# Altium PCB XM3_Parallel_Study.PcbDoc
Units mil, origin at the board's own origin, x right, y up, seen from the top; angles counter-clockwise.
Board outline 10000 x 11930 mil, 4 copper layers (TOP, LAYER2, LAYER3, BOTTOM), stack 92 mil thick; 58 components, 13 nets, 178 pads, 387 vias.
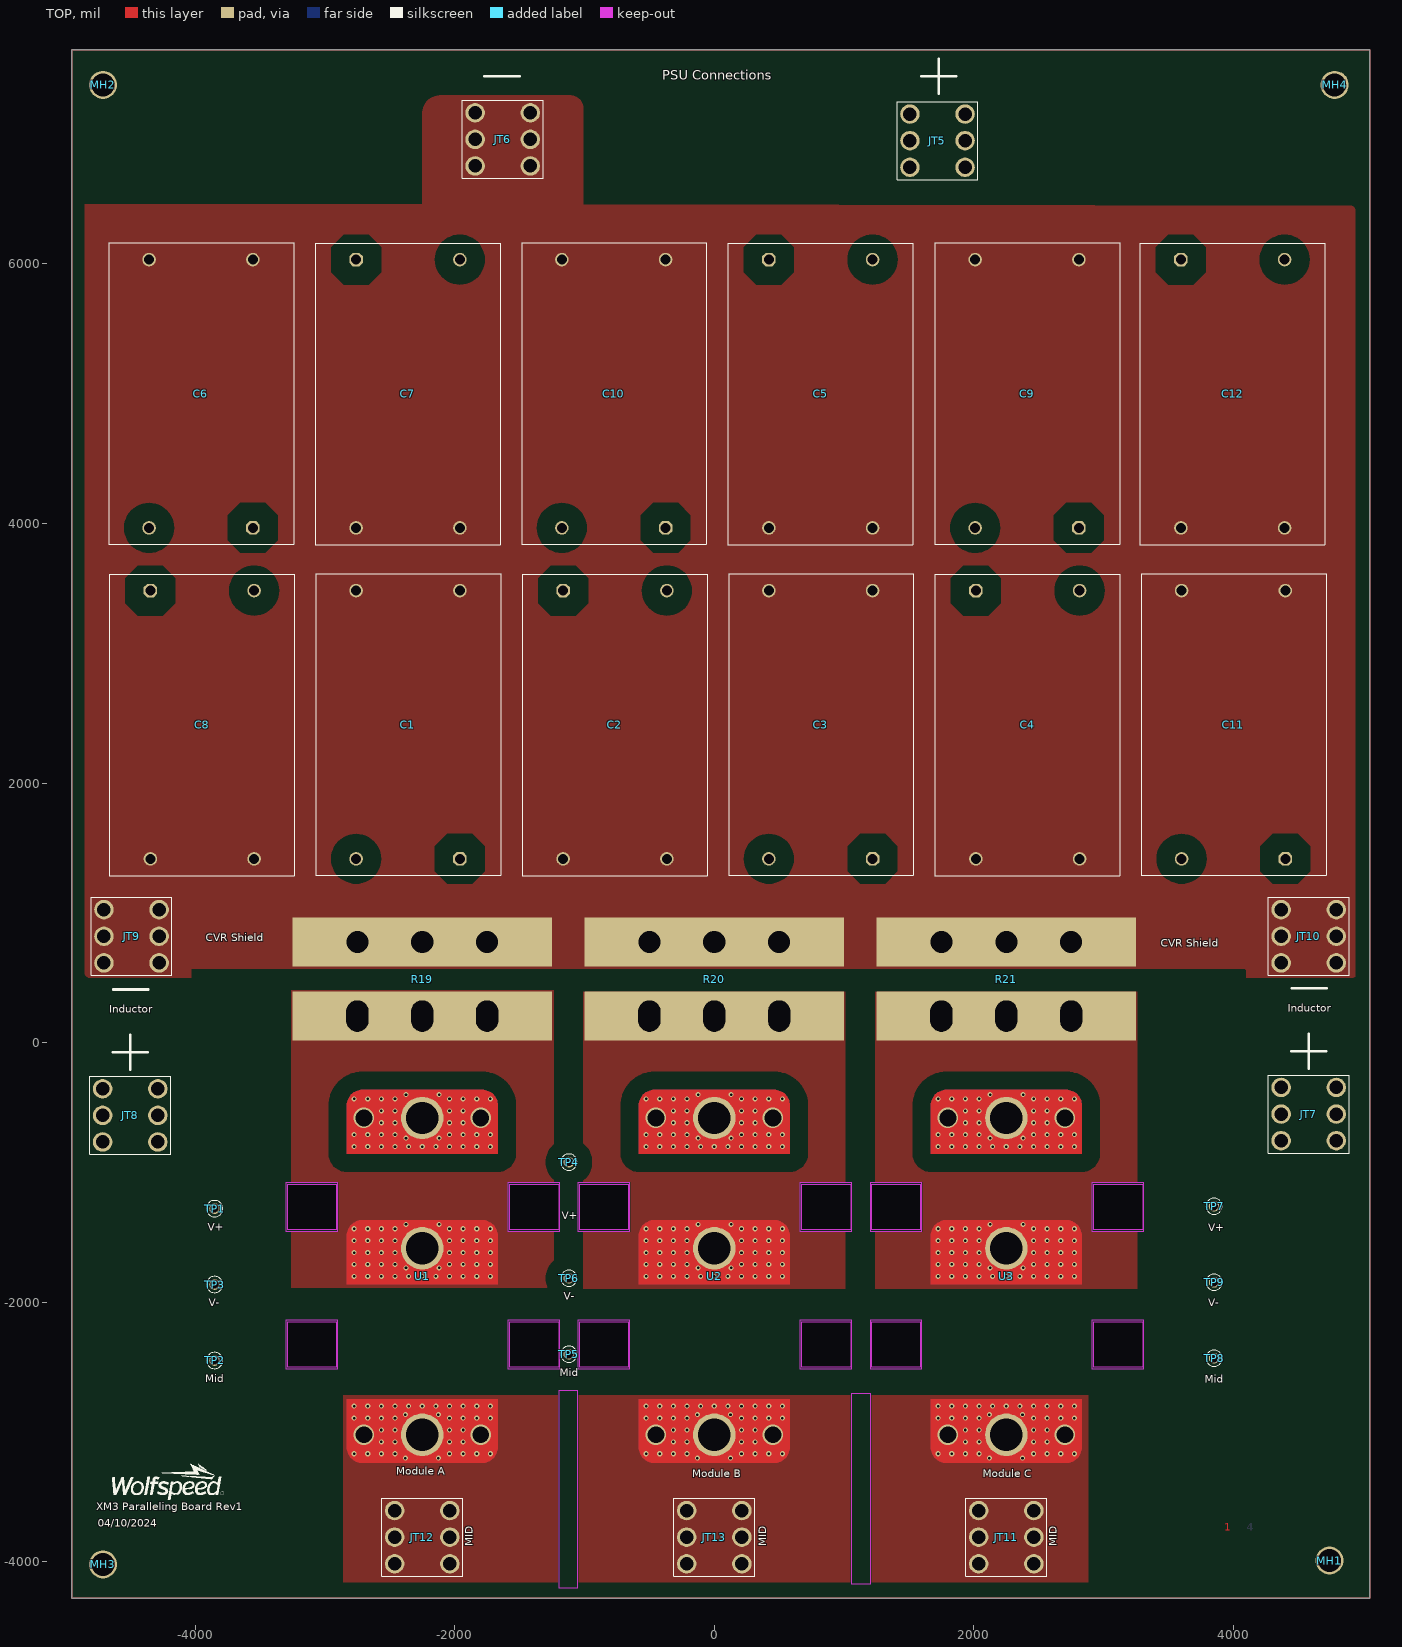
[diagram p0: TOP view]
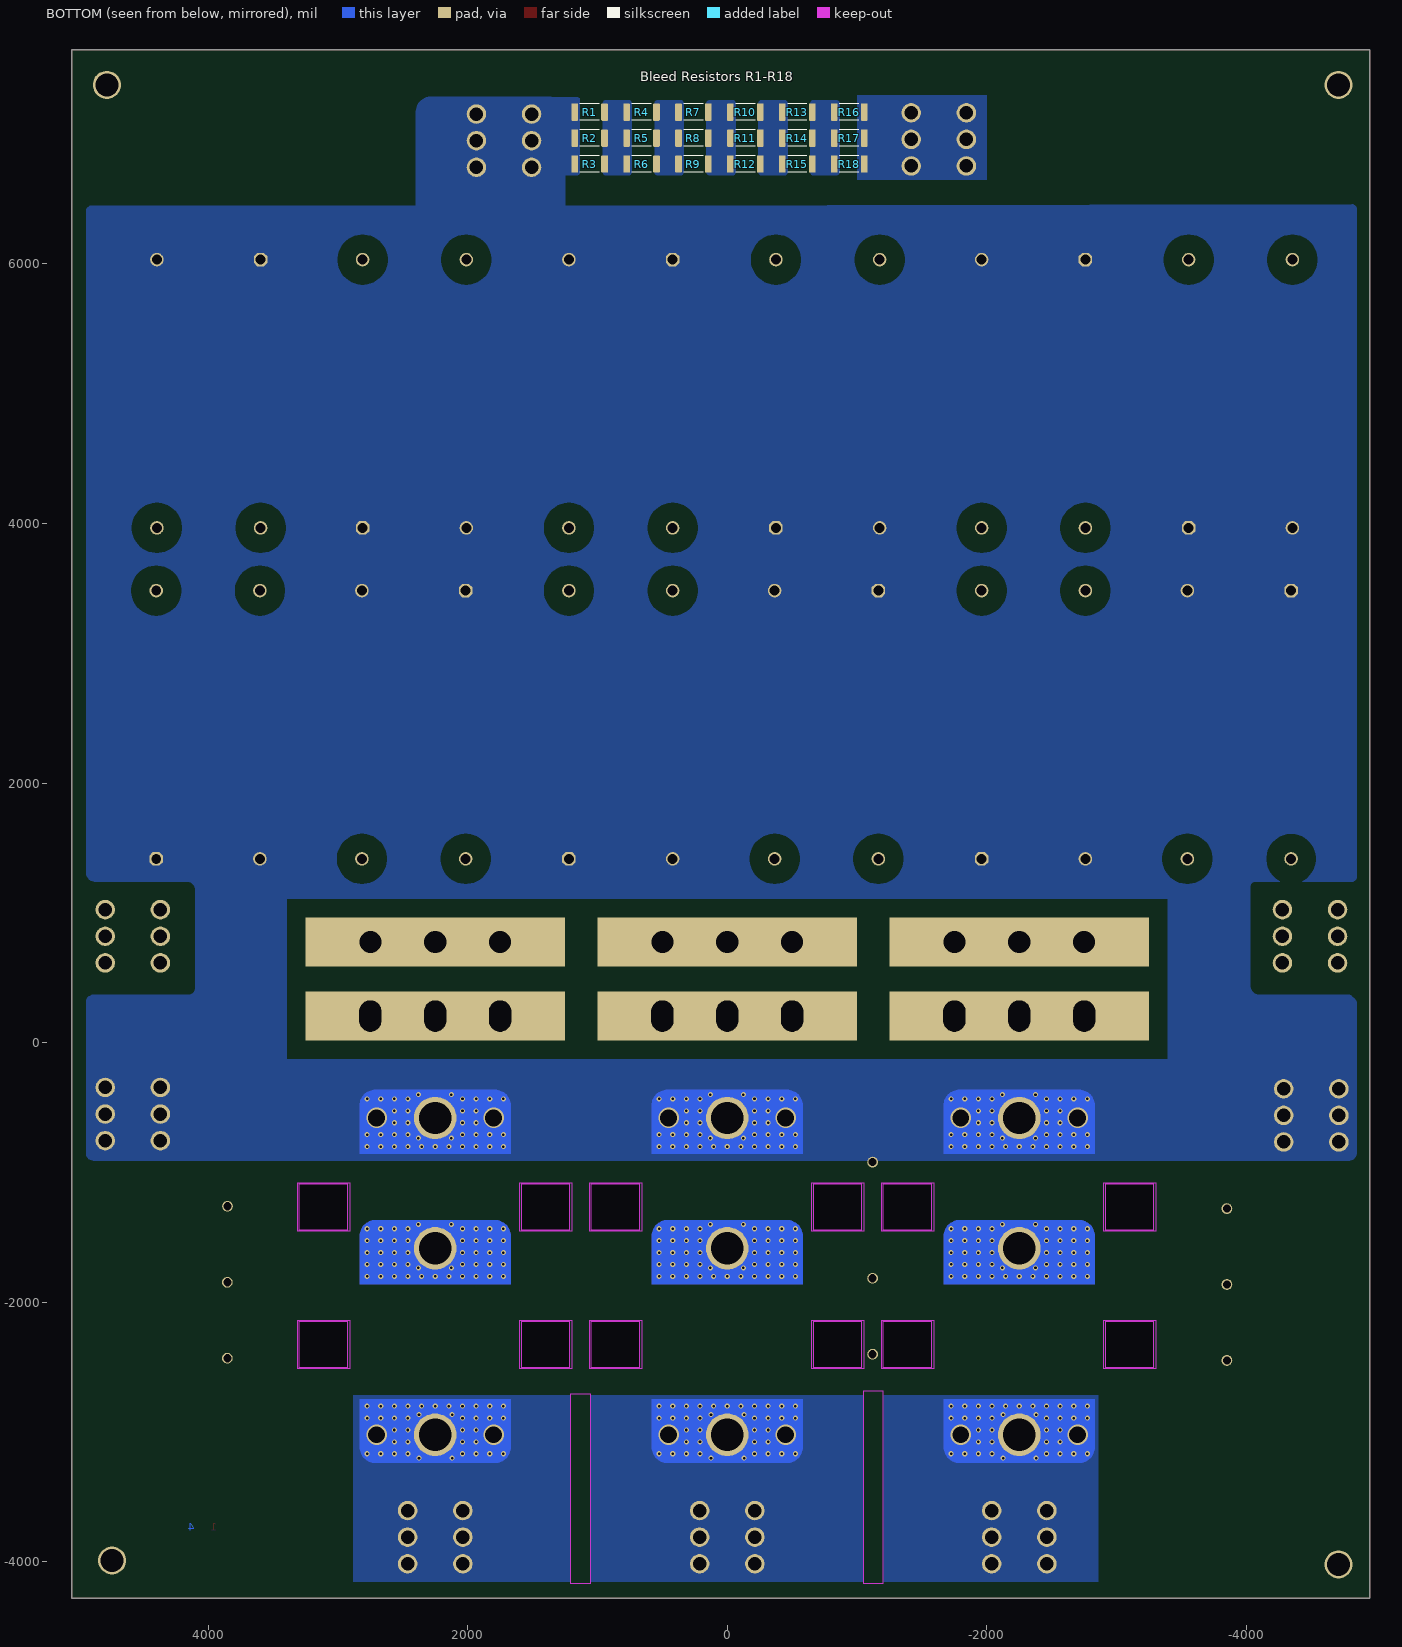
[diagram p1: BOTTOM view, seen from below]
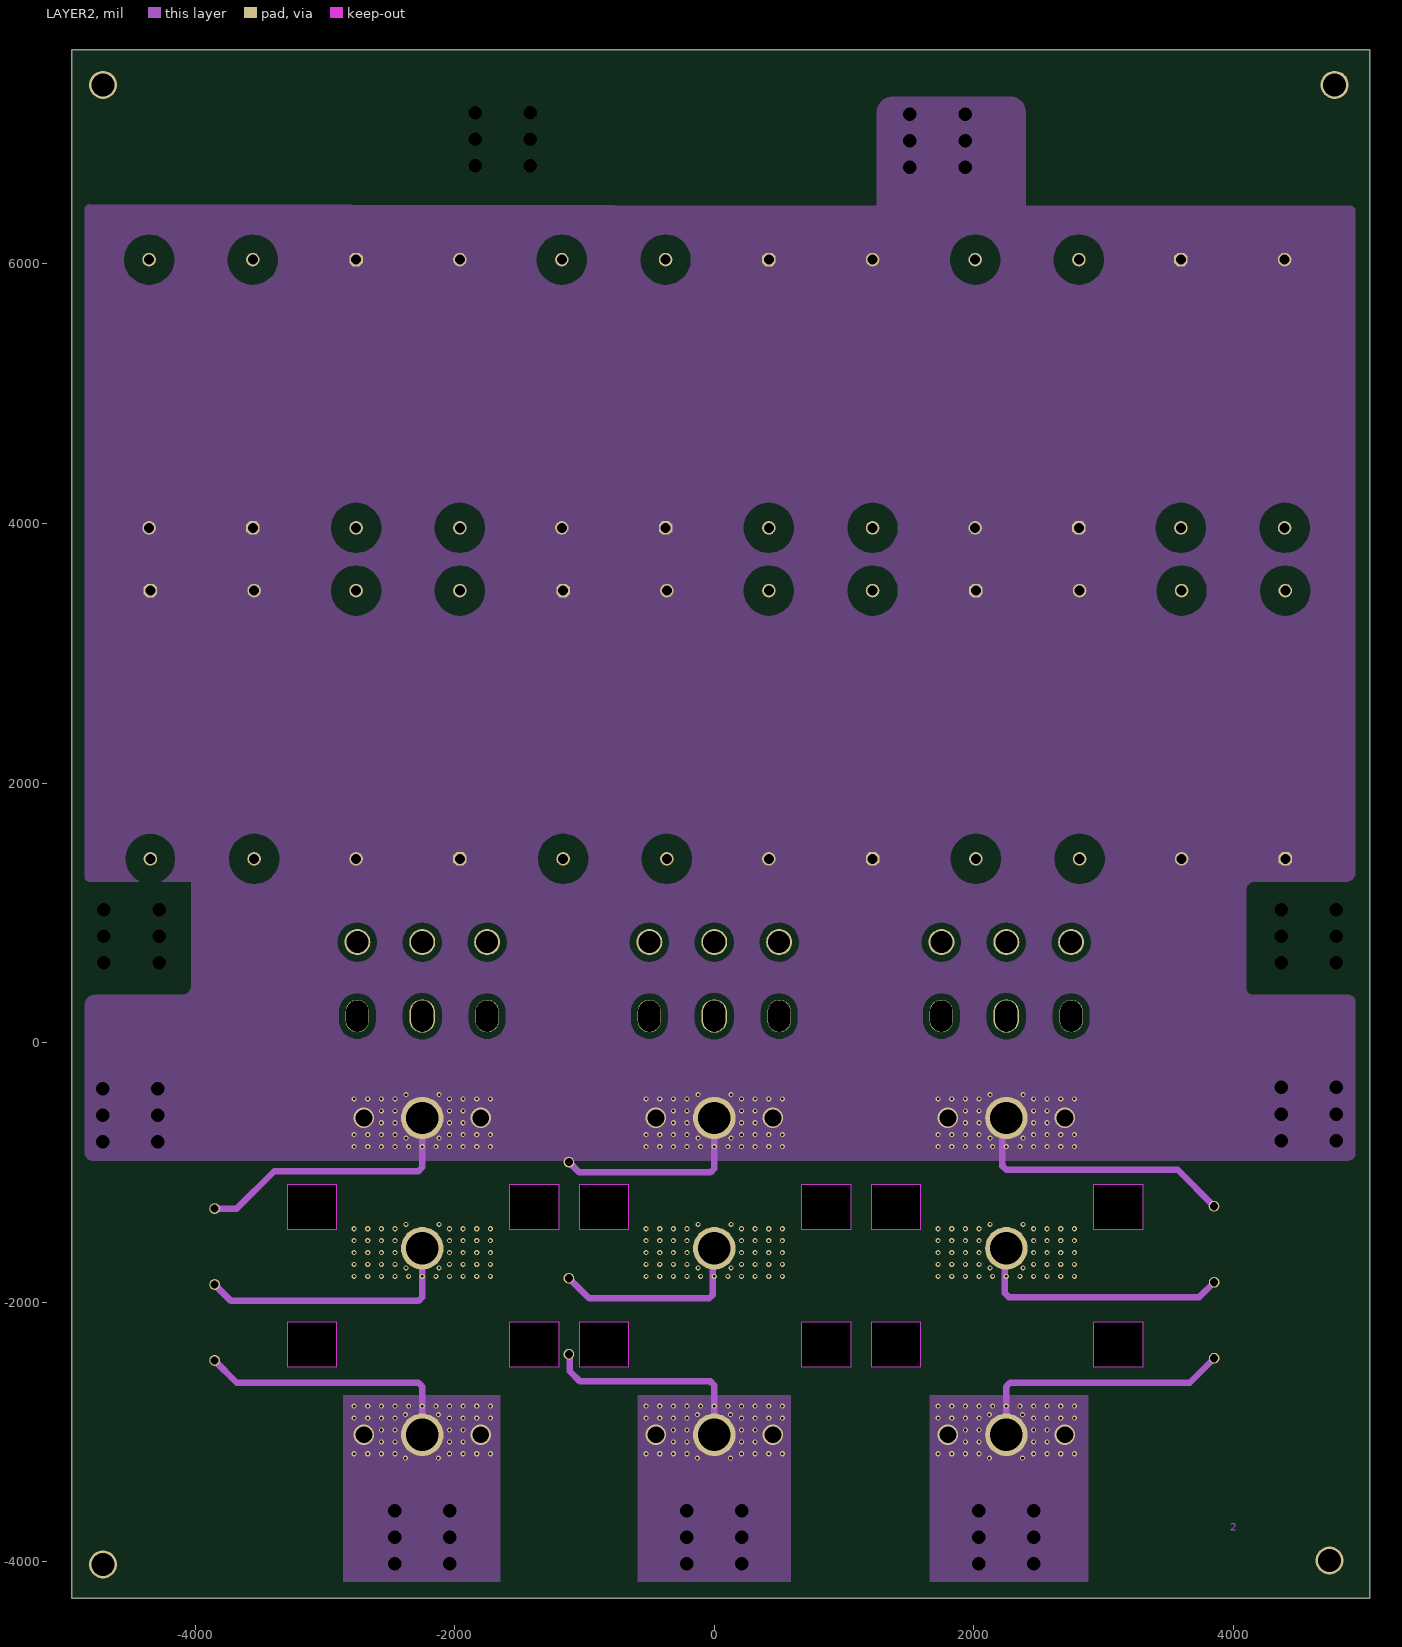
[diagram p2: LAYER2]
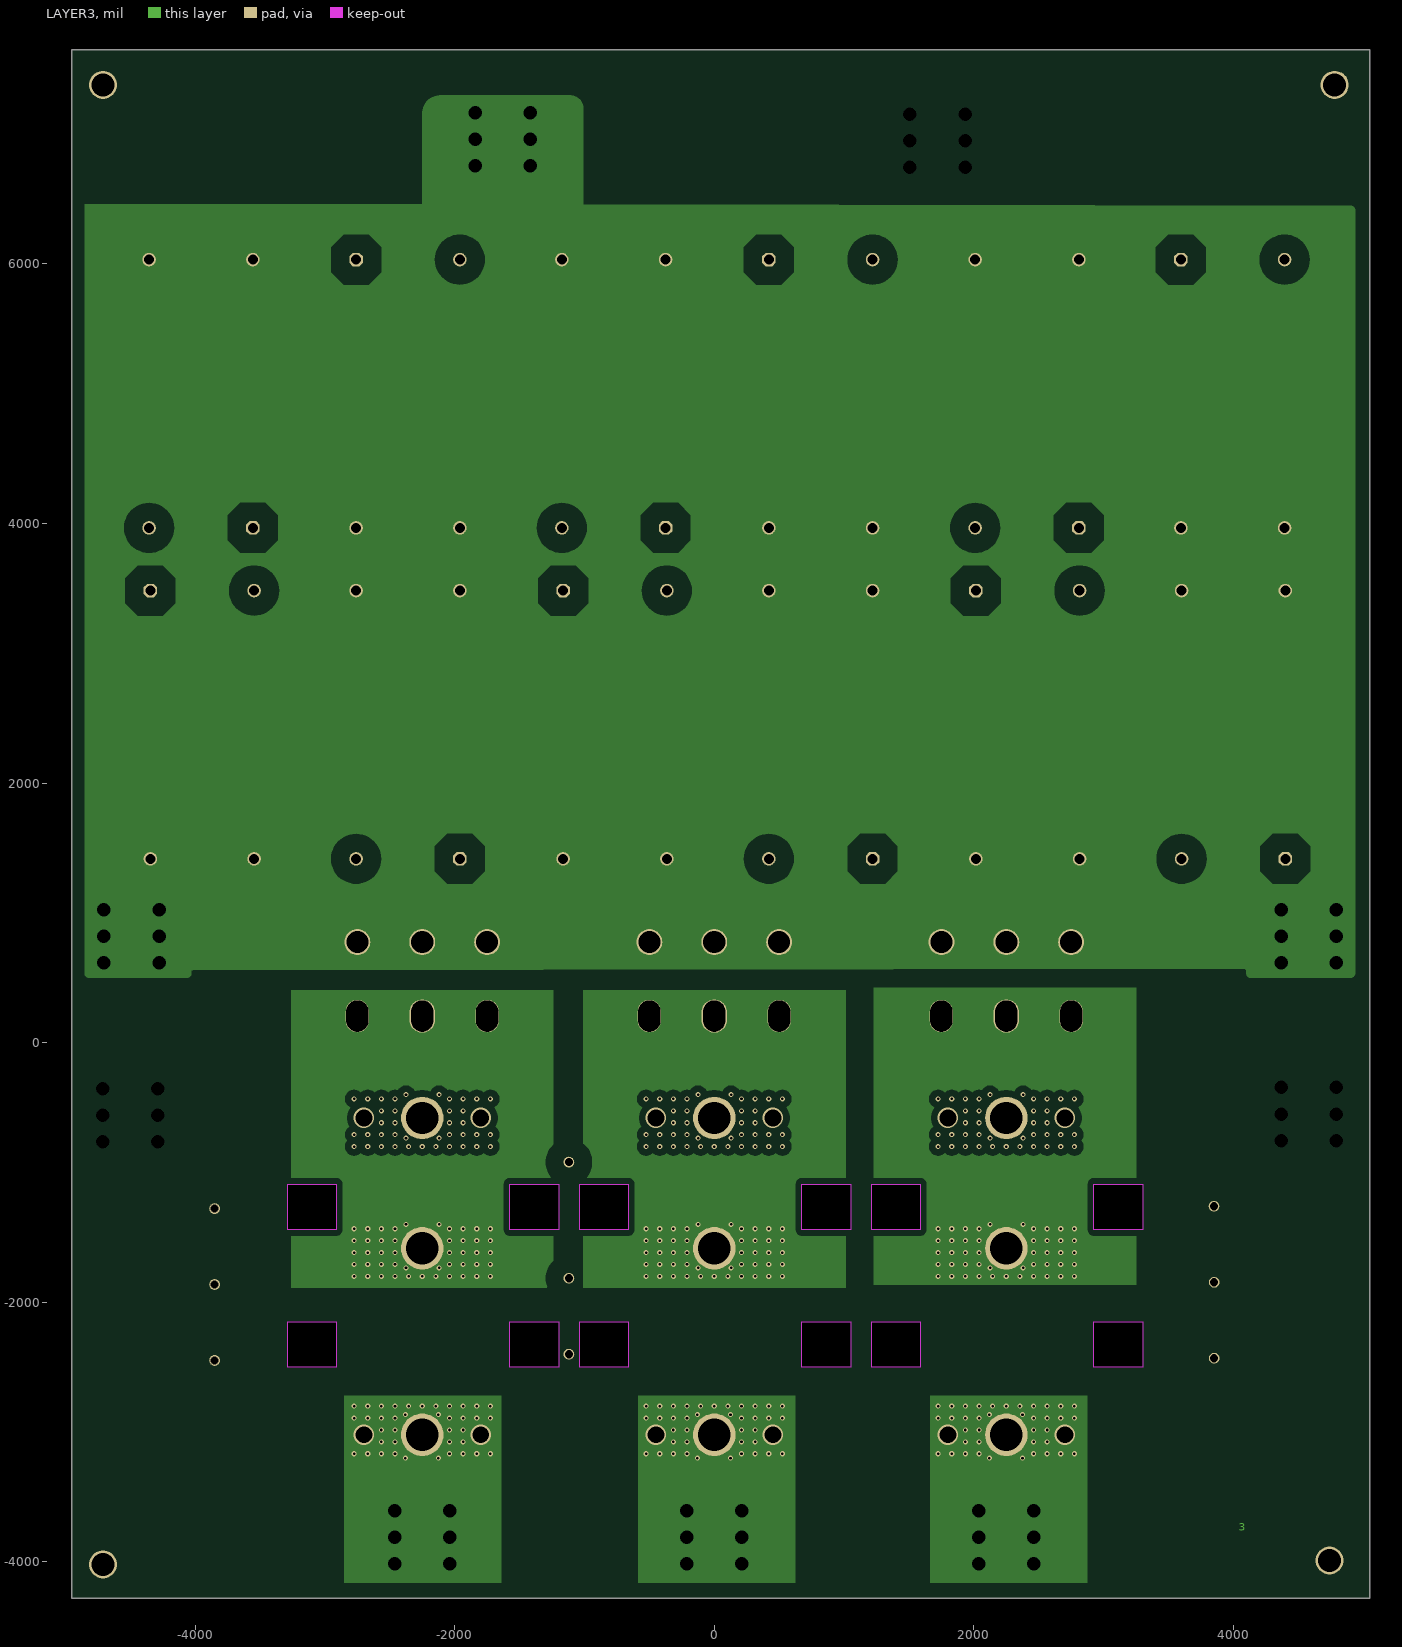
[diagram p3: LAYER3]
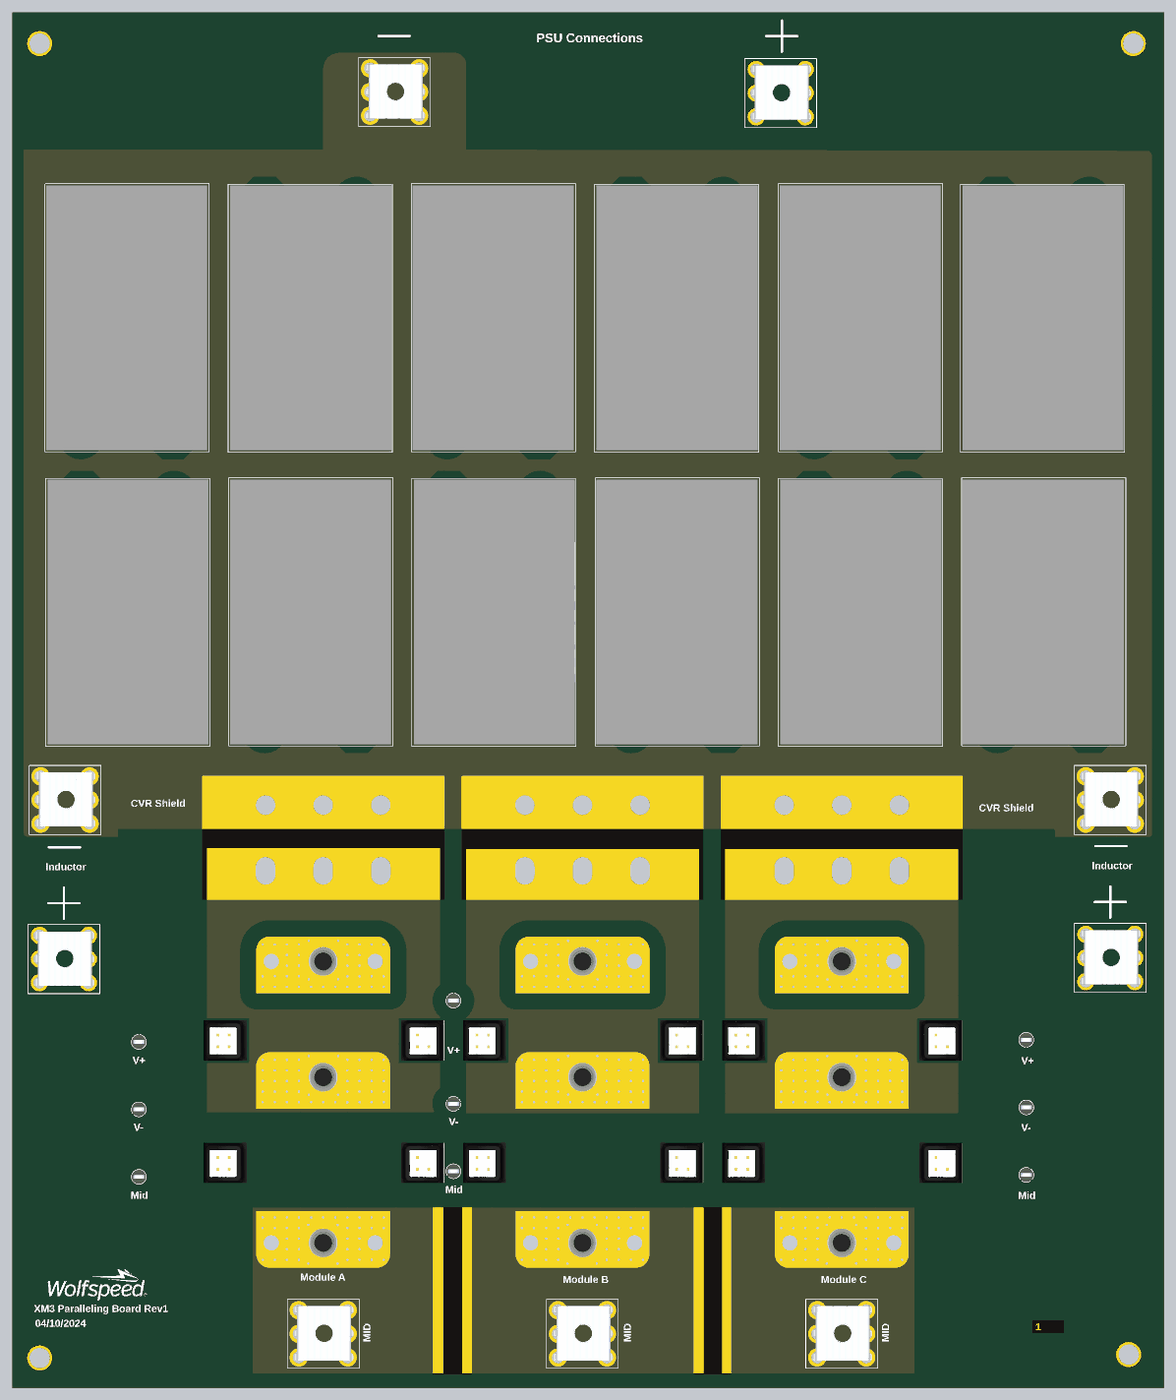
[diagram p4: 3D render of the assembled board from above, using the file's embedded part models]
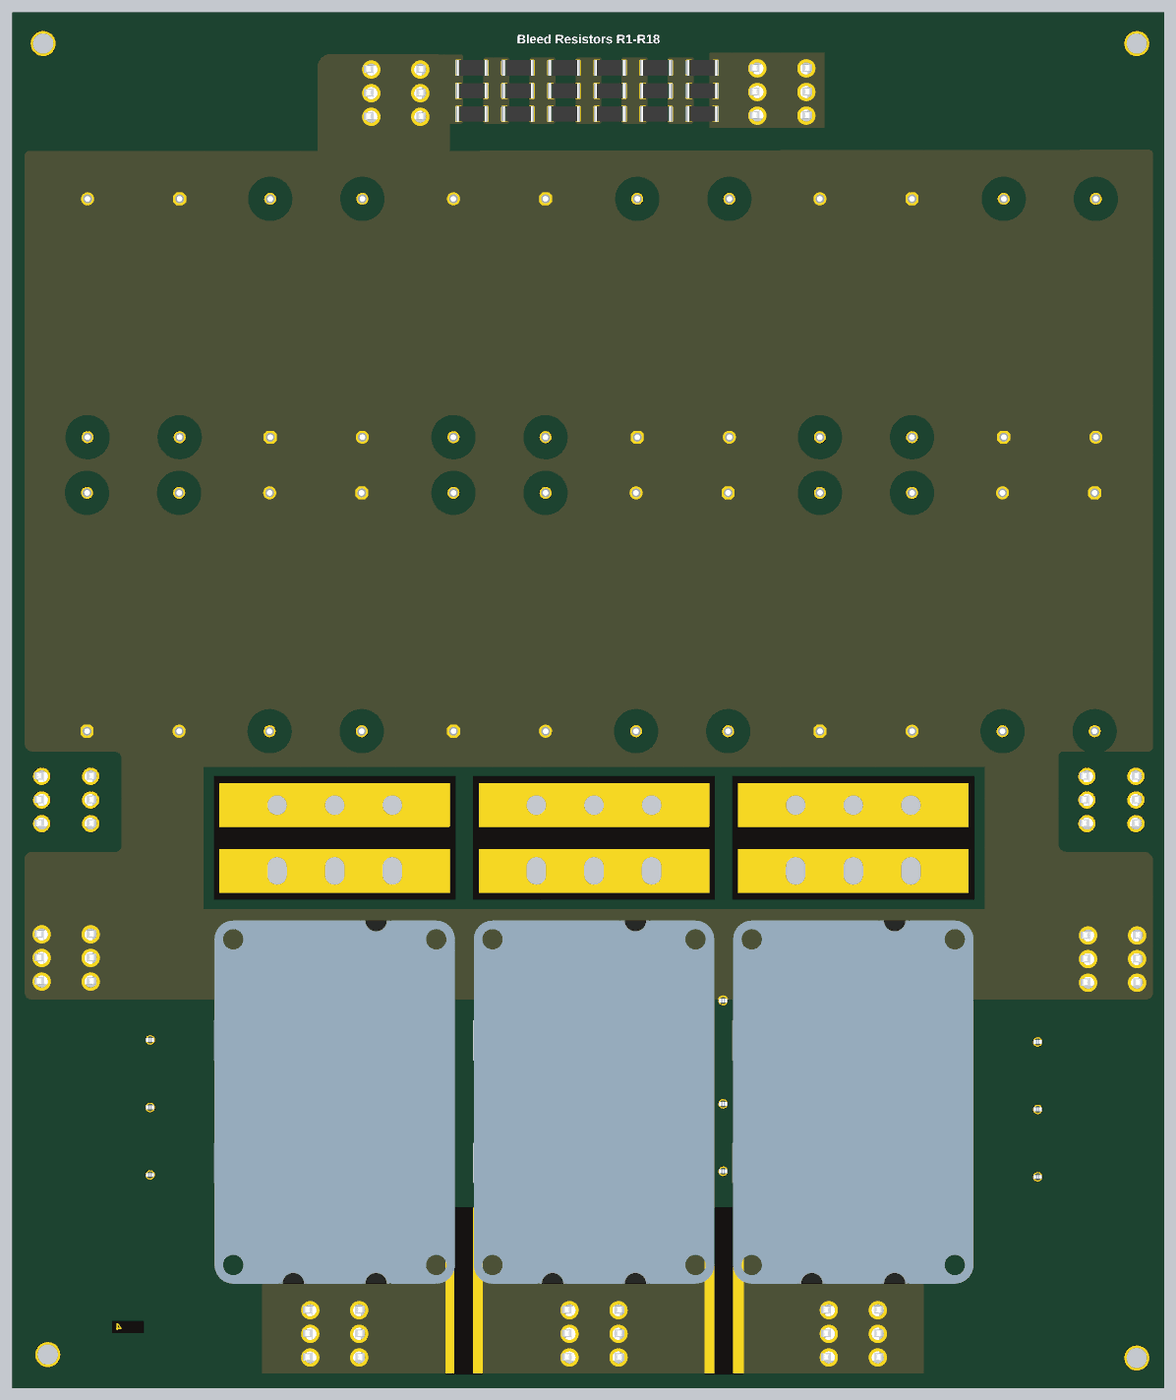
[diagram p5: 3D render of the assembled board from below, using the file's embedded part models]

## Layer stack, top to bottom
TOP: signal copper 2.68
Dielectric 1: core 8, FR-4, Dk 4.5
LAYER2: signal copper 2.68
Dielectric2: core 65.28, FR-4, Dk 4.5
LAYER3: signal copper 2.68
Dielectric3: core 8, FR-4, Dk 4.5
BOTTOM: signal copper 2.68

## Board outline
-4950,-4280 -4950,7650 5050,7650 5050,-4280

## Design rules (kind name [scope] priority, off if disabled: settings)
Clearance HiPot_Clearance_Inner2 [OnLayer('LAYER2') vs InComponent('R19') OR InComponent('R20') OR InComponent('R21') OR InComponent('U1')  OR InComponent('U2')  OR InComponent('U3')] p1: gap=50 ignorepadtopadclearanceinfootprint=TRUE
Clearance HiPot_Clearance_Inner3 [OnLayer('LAYER3') vs InComponent('R19') OR InComponent('R20') OR InComponent('R21') OR InComponent('U1')  OR InComponent('U2')  OR InComponent('U3')] p2: gap=50 ignorepadtopadclearanceinfootprint=TRUE
Clearance HiPot_Clearance [InNetClass('HighPotential') vs InNetClass('HighPotential')] p3: gap=140 ignorepadtopadclearanceinfootprint=TRUE
Clearance [All] p4: gap=6 ignorepadtopadclearanceinfootprint=FALSE
Height [All] p1: minheight=0 maxheight=3000 prefheight=500
HoleSize [All] p1: absolutevalues=TRUE maxlimit=1000 minlimit=1 maxpercent=80.000 minpercent=20.000
PlaneClearance [All] p1: clearance=275.59
PlaneConnect [All] p1: planeconnectstyle=Direct reliefexpansion=20 reliefentries=4 reliefconductorwidth=10 reliefairgap=10
PolygonConnect [All] p1: connectstyle=Direct reliefconductorwidth=10 reliefentries=4 polygonreliefangle="90 Angle" airgapwidth=10
RoutingVias [All] p1: holewidth=28 width=50 viastyle="Through Hole" minholewidth=5 minwidth=8 maxholewidth=28 maxwidth=50
SolderMaskExpansion [All] p1: expansion=4 istentingtop=FALSE
Width [All] p1: maxlimit=500 minlimit=5 preferedwidth=50 minimp=50.000000 maximp=50.000000 favimp=50.000000
26 further rules are at their usual default settings.

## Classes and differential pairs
net class HighPotential: +VIN -Vin Midpoint S1 S2 S3

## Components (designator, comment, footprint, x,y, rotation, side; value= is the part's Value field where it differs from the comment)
C1 "B32778G0406K000" C4AQSBW5220A3NJ -2360,2450 r180 top value=40uF
C2 "B32778G0406K000" C4AQSBW5220A3NJ -765,2450 r0 top value=40uF
C3 "B32778G0406K000" C4AQSBW5220A3NJ 820,2450 r180 top value=40uF
C4 "B32778G0406K000" C4AQSBW5220A3NJ 2415,2450 r0 top value=40uF
C5 "B32778G0406K000" C4AQSBW5220A3NJ 820,5000 r0 top value=40uF
C6 "B32778G0406K000" C4AQSBW5220A3NJ -3955,5000 r180 top value=40uF
C7 "B32778G0406K000" C4AQSBW5220A3NJ -2360,5000 r0 top value=40uF
C8 "B32778G0406K000" C4AQSBW5220A3NJ -3945,2450 r0 top value=40uF
C9 "B32778G0406K000" C4AQSBW5220A3NJ 2410,5000 r180 top value=40uF
C10 "B32778G0406K000" C4AQSBW5220A3NJ -775,5000 r180 top value=40uF
C11 "B32778G0406K000" C4AQSBW5220A3NJ 4000,2450 r180 top value=40uF
C12 "B32778G0406K000" C4AQSBW5220A3NJ 3995,5000 r0 top value=40uF
JT5 "8196" 8196 1720,6950 r90 top
JT6 "8196" 8196 -1630,6960 r90 top
JT7 "8196" 8196 4580,-550 r90 top
JT8 "8196" 8196 -4500,-560 r90 top
JT9 "8196" 8196 -4490,820 r90 top
JT10 "8196" 8196 4580,820 r90 top
JT11 "8196" 8196 2250,-3810 r90 top
JT12 "8196" 8196 -2250,-3810 r90 top
JT13 "8196" 8196 0,-3810 r90 top
MH1 "MountingHole" MountingHole4mm5#1 4740,-3990 r0 top
MH2 "MountingHole" MountingHole4mm5#2 -4710,7400 r0 top
MH3 "MountingHole" MountingHole4mm5#1 -4710,-4020 r0 top
MH4 "MountingHole" MountingHole4mm5#1 4780,7380 r0 top
R1 "2176071-6" RESC6432X06N 1060.43,7170 r180 bottom
R2 "2176071-6" RESC6432X06N 1060.43,6970 r180 bottom
R3 "2176071-6" RESC6432X06N 1060.43,6770 r180 bottom
R4 "2176071-6" RESC6432X06N 660.43,7170 r180 bottom
R5 "2176071-6" RESC6432X06N 660.43,6970 r180 bottom
R6 "2176071-6" RESC6432X06N 660.43,6770 r180 bottom
R7 "2176071-6" RESC6432X06N 260.43,7170 r180 bottom
R8 "2176071-6" RESC6432X06N 260.43,6970 r180 bottom
R9 "2176071-6" RESC6432X06N 260.43,6770 r180 bottom
R10 "2176071-6" RESC6432X06N -139.57,7170 r180 bottom
R11 "2176071-6" RESC6432X06N -139.57,6970 r180 bottom
R12 "2176071-6" RESC6432X06N -139.57,6770 r180 bottom
R13 "2176071-6" RESC6432X06N -539.57,7170 r180 bottom
R14 "2176071-6" RESC6432X06N -539.57,6970 r180 bottom
R15 "2176071-6" RESC6432X06N -539.57,6770 r180 bottom
R16 "2176071-6" RESC6432X06N -939.57,7170 r180 bottom
R17 "2176071-6" RESC6432X06N -939.57,6970 r180 bottom
R18 "2176071-6" RESC6432X06N -939.57,6770 r180 bottom
R19 "W-2-005-2FC" W-2-005-2FC_3HOLE -2250,480 r180 top
R20 "W-2-005-2FC" W-2-005-2FC_3HOLE 0,480 r180 top
R21 "W-2-005-2FC" W-2-005-2FC_3HOLE 2250,480 r180 top
TP1 "5011" KSTN-5011_V -3850,-1278.23 r0 top
TP2 "5011" KSTN-5011_V -3850,-2448.23 r0 top
TP3 "5011" KSTN-5011_V -3850,-1863.23 r0 top
TP4 "5011" KSTN-5011_V -1120,-920 r0 top
TP5 "5011" KSTN-5011_V -1120,-2400 r0 top
TP6 "5011" KSTN-5011_V -1120,-1815 r0 top
TP7 "5011" KSTN-5011_V 3850.76,-1260.29 r0 top
TP8 "5011" KSTN-5011_V 3851.53,-2431.06 r0 top
TP9 "5011" KSTN-5011_V 3851.53,-1846.06 r0 top
U1 "XM_Module" "XM MODULE" -2250,-1800.47 r0 top
U2 "XM_Module" "XM MODULE" 0,-1800.47 r0 top
U3 "XM_Module" "XM MODULE" 2250,-1800.47 r0 top

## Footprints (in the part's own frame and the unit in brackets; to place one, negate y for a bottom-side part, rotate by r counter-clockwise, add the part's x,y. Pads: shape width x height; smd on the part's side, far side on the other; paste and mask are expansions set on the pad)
8196 [mil]
  round 150 / inner round 60 / far side round 150 hole 103.94: 1(-205,-212.5) 2(0,-212.5) 3(205,-212.5) 4(205,212.5) 5(0,212.5) 6(-205,212.5)
  silkscreen extent -300,-312 300,312, body extent -230,-278 240,262, height 454
C4AQSBW5220A3NJ [mm] "C4AQSBW5220A3NJ Unchecked Film; Metallized Polypropylene; DC Link; C4AQ; Automotive Grade; 22 uF; 5%; 1; 50 Film Capacitors 8.13"
  oct 2.65x2.65 hole 1.95: 1(-10.15,26.25)
  round 2.65 hole 1.95: 2(10.15,26.25) 3(-10.15,-26.25) 4(10.15,-26.25)
  silkscreen extent -18.16,-29.59 18.03,29.46, body extent -17.73,-29.15 17.78,29.15, height 50.31
KSTN-5011_V [mm] "Test Point, Dia 3.17mm"
  round 2.1 hole 1.6: 1(0,0)
  silkscreen extent -1.59,-1.58 1.59,1.58, body extent -1.59,-1.59 1.59,1.59, height 8.13
MountingHole4mm5#1 [mm]
  round 5.5 hole 4.5: 3(0,0)
MountingHole4mm5#2 [mm]
  round 5.5 hole 4.5: 3(0,-0.508)
RESC6432X06N [mm] "Chip Resistor, 2-Leads, Body 6.35x3.20mm, IPC Medium Density"
  rrect25% 1.3x3.4 smd: 1(-2.925,0) 2(2.925,0)
  silkscreen extent -1.9,-1.6 1.9,1.6, body extent -3.22,-1.7 3.22,1.7, height 0.65
W-2-005-2FC_3HOLE [mil]
  oval 180x250 hole 170 slot 240 at 90 deg: 1(-500,275) 3(500,275)
  rect 2000x380 / inner oval 196.85x255.91 / far side rect 2000x380 hole 170 slot 240 at 90 deg: 2(0,275)
  round 200 hole 170: 4(-500,-295.28) 6(500,-295.28)
  rect 2000x380 / inner round 200 / far side rect 2000x380 hole 170: 5(0,-295.28)
"XM MODULE" [mm]
  round 8.3 hole 6.3: 1(0,-31) 2(0,5.5) 3(0,31)
  TOP region: -14.75,-24 14.75,-24 14.75,-33.452 14.518,-34.618 13.857,-35.607 12.868,-36.268 11.702,-36.5 11.702,-36.5 -11.702,-36.5 -12.868,-36.268 -13.857,-35.607 -14.518,-34.618 -14.75,-33.452 -14.75,-33.452 -14.75,-25
  TOP region: -14.75,-24 14.75,-24 14.75,-33.452 14.518,-34.618 13.857,-35.607 12.868,-36.268 11.702,-36.5 11.702,-36.5 -11.702,-36.5 -12.868,-36.268 -13.857,-35.607 -14.518,-34.618 -14.75,-33.452 -14.75,-33.452 -14.75,-25
  TOP region: -14.75,24 14.768,24 14.768,33.452 14.536,34.618 13.875,35.607 12.886,36.268 11.72,36.5 11.72,36.5 -11.702,36.5 -12.868,36.268 -13.857,35.607 -14.518,34.618 -14.75,33.452 -14.75,33.452 -14.75,28.75
  TOP region: -14.75,-1.5 14.75,-1.5 14.75,7.952 14.518,9.118 13.857,10.107 12.868,10.768 11.702,11 11.702,11 -11.702,11 -12.868,10.768 -13.857,10.107 -14.518,9.118 -14.75,7.952 -14.75,7.952 -14.75,2.236
  TOP keep-out region: -26.67,8.801 -16.51,8.801 -16.51,18.326 -26.67,18.326
  TOP keep-out region: 16.764,8.801 26.924,8.801 26.924,18.326 16.764,18.326
  TOP keep-out region: 16.764,-18.098 26.924,-18.098 26.924,-8.572 16.764,-8.572
  TOP keep-out region: -26.67,-18.098 -16.51,-18.098 -16.51,-8.572 -26.67,-8.572
  BOTTOM region: -14.75,24 14.768,24 14.768,33.452 14.536,34.618 13.875,35.607 12.886,36.268 11.72,36.5 11.72,36.5 -11.702,36.5 -12.868,36.268 -13.857,35.607 -14.518,34.618 -14.75,33.452 -14.75,33.452 -14.75,28.75
  BOTTOM region: -14.75,-1.5 14.75,-1.5 14.75,7.952 14.518,9.118 13.857,10.107 12.868,10.768 11.702,11 11.702,11 -11.702,11 -12.868,10.768 -13.857,10.107 -14.518,9.118 -14.75,7.952 -14.75,7.952 -14.75,2.236
  BOTTOM region: -14.75,-24 14.75,-24 14.75,-33.452 14.518,-34.618 13.857,-35.607 12.868,-36.268 11.702,-36.5 11.702,-36.5 -11.702,-36.5 -12.868,-36.268 -13.857,-35.607 -14.518,-34.618 -14.75,-33.452 -14.75,-33.452 -14.75,-25
  BOTTOM keep-out region: 16.764,8.801 26.924,8.801 26.924,18.326 16.764,18.326
  BOTTOM keep-out region: 16.764,-18.098 26.924,-18.098 26.924,-8.572 16.764,-8.572
  BOTTOM keep-out region: -26.67,-18.098 -16.51,-18.098 -16.51,-8.572 -26.67,-8.572
  BOTTOM keep-out region: -26.67,8.801 -16.51,8.801 -16.51,18.326 -26.67,18.326
  Keep-Out Layer board cut-out: 17.145,18.034 26.67,18.034 26.67,9.144 17.145,9.144
  Keep-Out Layer board cut-out: 17.145,-8.89 26.67,-8.89 26.67,-17.78 17.145,-17.78
  Keep-Out Layer board cut-out: -26.352,-8.89 -16.828,-8.89 -16.828,-17.78 -26.352,-17.78
  Keep-Out Layer board cut-out: -26.352,18.034 -16.828,18.034 -16.828,9.144 -26.352,9.144
  body extent -26.5,-40 26.5,40, height 15.76

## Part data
C1 C2 C3 C4 C5 C6 C7 C8 C9 C10 C11 C12: "B32778G0406K000 Unchecked Film; Metallized Polypropylene; DC Link; C4AQ; Automotive Grade; 40 uF; 5%; 1; 50 Film Capacitors 8.13", Manufacturer=Kemet, Tolerence=5%, Voltage Rating=1500VDC
JT5 JT6 JT7 JT8 JT9 JT10 JT11 JT12 JT13: library part "Conn Plug 6", "TERMINAL SCREW PC HEAVY DUTY", Manufacturer="Keystone Electronics"
R1 R2 R3 R4 R5 R6 R7 R8 R9 R10 R11 R12 R13 R14 R15 R16 R17 R18: "Res Thick Film 2512 220K Ohm 1% 2W ±100ppm/°C Molded SMD T/R", Case Code (Imperial)=2512, Case Code (Metric)=6432, Manufacturer="TE Connectivity", Max Operating Temperature=155°C, Max Power Dissipation=2W, Min Operating Temperature=-55°C, Package Quantity=4000, Resistance=220kR, Resistor Type="Thick Film", Supplier Part Number 1=01AH0733, Temperature Coefficient=100ppm/°C, Tolerance=1%
TP1 TP2 TP3 TP4 TP5 TP6 TP7 TP8 TP9: "Test Point, Black, Through Hole, RoHS, Bulk", Colour=Black, Manufacturer=Keystone, Package Quantity=100

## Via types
v1: diameter 39.37, hole 19.68, TOP to BOTTOM, 375 vias
v2: diameter 157.48, hole 129.92, TOP to BOTTOM, 12 vias

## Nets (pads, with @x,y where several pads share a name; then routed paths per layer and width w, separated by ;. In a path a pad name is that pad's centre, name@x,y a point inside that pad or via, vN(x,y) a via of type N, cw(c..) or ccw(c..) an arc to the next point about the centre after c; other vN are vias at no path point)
+VIN: C1.1 C1.2 C2.1 C2.2 C3.1 C3.2 C4.1 C4.2 C5.1 C5.2 C6.1 C6.2 C7.1 C7.2 C8.1 C8.2 C9.1 C9.2 C10.1 C10.2 C11.1 C11.2 C12.1 C12.2 JT5.1 JT5.2 JT5.3 JT5.4 JT5.5 JT5.6 JT7.1 JT7.2 JT7.3 JT7.4 JT7.5 JT7.6 JT8.1 JT8.2 JT8.3 JT8.4 JT8.5 JT8.6 R1.1 R2.1 R3.1 TP1.1 TP4.1 TP7.1 U1.3 U2.3 U3.3 | length 5810.4
  LAYER2 w50: TP1.1 -3678.23,-1278.23 -3390,-990 -2279.29,-990 -2250,-960.71 v1(-2250,-800.47) U1.3 ; TP4.1 -1040,-1000 -29.29,-1000 0,-970.71 v1(0,-800.47) U2.3 ; U3.3 2220,-610 2220,-950.71 2249.29,-980 3570.47,-980 TP7.1
  other v1: -2775,-800.47 -2670,-800.47 -2565,-800.47 -2460,-800.47 -2355,-800.47 -2145,-800.47 -2040,-800.47 -1935,-800.47 -1830,-800.47 -1725,-800.47 -525,-800.47 -420,-800.47 -315,-800.47 -210,-800.47 -105,-800.47 105,-800.47 210,-800.47 315,-800.47 420,-800.47 525,-800.47 1725,-800.47 1830,-800.47 1935,-800.47 2040,-800.47 2145,-800.47 2250,-800.47 2355,-800.47 2460,-800.47 2565,-800.47 2670,-800.47 2775,-800.47 -2375,-735.51 -2120.08,-735.51 -125,-735.51 129.92,-735.51 2125,-735.51 2379.92,-735.51 -2775,-708.69 -2670,-708.69 -2565,-708.69 -2460,-708.69 -2040,-708.69 -1935,-708.69 -1830,-708.69 -1725,-708.69 -525,-708.69 -420,-708.69 -315,-708.69 -210,-708.69 210,-708.69 315,-708.69 420,-708.69 525,-708.69 1725,-708.69 1830,-708.69 1935,-708.69 2040,-708.69 2460,-708.69 2565,-708.69 2670,-708.69 2775,-708.69 -2565,-616.91 -2460,-616.91 -2040,-616.91 -1935,-616.91 -315,-616.91 -210,-616.91 210,-616.91 315,-616.91 1935,-616.91 2040,-616.91 2460,-616.91 2565,-616.91 -2565,-525.13 -2460,-525.13 -2040,-525.13 -1935,-525.13 -315,-525.13 -210,-525.13 210,-525.13 315,-525.13 1935,-525.13 2040,-525.13 2460,-525.13 2565,-525.13 -2775,-433.34 -2670,-433.34 -2565,-433.34 -2460,-433.34 -2040,-433.34 -1935,-433.34 -1830,-433.34 -1725,-433.34 -525,-433.34 -420,-433.34 -315,-433.34 -210,-433.34 210,-433.34 315,-433.34 420,-433.34 525,-433.34 1725,-433.34 1830,-433.34 1935,-433.34 2040,-433.34 2460,-433.34 2565,-433.34 2670,-433.34 2775,-433.34 -2375,-400.47 -2120.08,-400.47 -125,-400.47 129.92,-400.47 2125,-400.47 2379.92,-400.47
  other v2: -2700,-580 -1798.7,-580 -450,-580 451.3,-580 1800,-580 2701.3,-580
-Vin: C1.3 C1.4 C2.3 C2.4 C3.3 C3.4 C4.3 C4.4 C5.3 C5.4 C6.3 C6.4 C7.3 C7.4 C8.3 C8.4 C9.3 C9.4 C10.3 C10.4 C11.3 C11.4 C12.3 C12.4 JT6.1 JT6.2 JT6.3 JT6.4 JT6.5 JT6.6 JT9.1 JT9.2 JT9.3 JT9.4 JT9.5 JT9.6 JT10.1 JT10.2 JT10.3 JT10.4 JT10.5 JT10.6 R16.2 R17.2 R18.2 R19.4 R19.5 R19.6 R20.4 R20.5 R20.6 R21.4 R21.5 R21.6
MidpointA: JT12.1 JT12.2 JT12.3 JT12.4 JT12.5 JT12.6 TP2.1 U1.1 | length 2054.9
  LAYER2 w50: TP2.1 -3678.23,-2620 -2279.29,-2620 -2250,-2649.29 v1(-2250,-2800.47) U1.1
  other v1: -2379.92,-3200.47 -2125,-3200.47 -2775,-3167.6 -2670,-3167.6 -2565,-3167.6 -2460,-3167.6 -2040,-3167.6 -1935,-3167.6 -1830,-3167.6 -1725,-3167.6 -2565,-3075.81 -2460,-3075.81 -2040,-3075.81 -1935,-3075.81 -2565,-2984.03 -2460,-2984.03 -2040,-2984.03 -1935,-2984.03 -2775,-2892.25 -2670,-2892.25 -2565,-2892.25 -2460,-2892.25 -2040,-2892.25 -1935,-2892.25 -1830,-2892.25 -1725,-2892.25 -2379.92,-2865.43 -2125,-2865.43 -2775,-2800.47 -2670,-2800.47 -2565,-2800.47 -2460,-2800.47 -2355,-2800.47 -2145,-2800.47 -2040,-2800.47 -1935,-2800.47 -1830,-2800.47 -1725,-2800.47
  other v2: -2700,-3020.94 -1798.7,-3020.94
MidpointB: JT13.1 JT13.2 JT13.3 JT13.4 JT13.5 JT13.6 TP5.1 U2.1 | length 1673.4
  LAYER2 w50: TP5.1 -1113.75,-2406.25 -1113.75,-2429.36 -1112.5,-2430.61 -1112.5,-2531.54 -1034.04,-2610 -29.29,-2610 0,-2639.29 v1(0,-2800.47) U2.1
  other v1: -129.92,-3200.47 125,-3200.47 -525,-3167.6 -420,-3167.6 -315,-3167.6 -210,-3167.6 210,-3167.6 315,-3167.6 420,-3167.6 525,-3167.6 -315,-3075.81 -210,-3075.81 210,-3075.81 315,-3075.81 -315,-2984.03 -210,-2984.03 210,-2984.03 315,-2984.03 -525,-2892.25 -420,-2892.25 -315,-2892.25 -210,-2892.25 210,-2892.25 315,-2892.25 420,-2892.25 525,-2892.25 -129.92,-2865.43 125,-2865.43 -525,-2800.47 -420,-2800.47 -315,-2800.47 -210,-2800.47 -105,-2800.47 105,-2800.47 210,-2800.47 315,-2800.47 420,-2800.47 525,-2800.47
  other v2: -450,-3020.94 451.3,-3020.94
MidpointC: JT11.1 JT11.2 JT11.3 JT11.4 JT11.5 JT11.6 TP8.1 U3.1 | length 2063.6
  LAYER2 w50: U3.1 v1(2250,-2800.47) 2250,-2649.29 2279.29,-2620 3662.6,-2620 TP8.1
  other v1: 2120.08,-3200.47 2375,-3200.47 1725,-3167.6 1830,-3167.6 1935,-3167.6 2040,-3167.6 2460,-3167.6 2565,-3167.6 2670,-3167.6 2775,-3167.6 1935,-3075.81 2040,-3075.81 2460,-3075.81 2565,-3075.81 1935,-2984.03 2040,-2984.03 2460,-2984.03 2565,-2984.03 1725,-2892.25 1830,-2892.25 1935,-2892.25 2040,-2892.25 2460,-2892.25 2565,-2892.25 2670,-2892.25 2775,-2892.25 2120.08,-2865.43 2375,-2865.43 1725,-2800.47 1830,-2800.47 1935,-2800.47 2040,-2800.47 2145,-2800.47 2355,-2800.47 2460,-2800.47 2565,-2800.47 2670,-2800.47 2775,-2800.47
  other v2: 1800,-3020.94 2701.3,-3020.94
NetR1_2: R1.2 R2.2 R3.2 R4.1 R5.1 R6.1
NetR4_2: R4.2 R5.2 R6.2 R7.1 R8.1 R9.1
NetR7_2: R7.2 R8.2 R9.2 R10.1 R11.1 R12.1
NetR10_2: R10.2 R11.2 R12.2 R13.1 R14.1 R15.1
NetR13_2: R13.2 R14.2 R15.2 R16.1 R17.1 R18.1
S1: R19.1 R19.2 R19.3 TP3.1 U1.2 | length 2041.4
  LAYER2 w50: TP3.1 -3723.23,-1990 -2279.29,-1990 -2250,-1960.71 v1(-2250,-1800.47) U1.2
  other v1: -2775,-1800.47 -2670,-1800.47 -2565,-1800.47 -2460,-1800.47 -2355,-1800.47 -2145,-1800.47 -2040,-1800.47 -1935,-1800.47 -1830,-1800.47 -1725,-1800.47 -2375,-1735.51 -2120.08,-1735.51 -2775,-1708.69 -2670,-1708.69 -2565,-1708.69 -2460,-1708.69 -2040,-1708.69 -1935,-1708.69 -1830,-1708.69 -1725,-1708.69 -2775,-1616.91 -2670,-1616.91 -2565,-1616.91 -2460,-1616.91 -2040,-1616.91 -1935,-1616.91 -1830,-1616.91 -1725,-1616.91 -2775,-1525.13 -2670,-1525.13 -2565,-1525.13 -2460,-1525.13 -2040,-1525.13 -1935,-1525.13 -1830,-1525.13 -1725,-1525.13 -2775,-1433.34 -2670,-1433.34 -2565,-1433.34 -2460,-1433.34 -2040,-1433.34 -1935,-1433.34 -1830,-1433.34 -1725,-1433.34 -2375,-1400.47 -2120.08,-1400.47
S2: R20.1 R20.2 R20.3 TP6.1 U2.2 | length 1547.3
  LAYER2 w50: TP6.1 -965,-1970 -39.29,-1970 -10,-1940.71 -10,-1593.93 U2.2
  other v1: -525,-1800.47 -420,-1800.47 -315,-1800.47 -210,-1800.47 -105,-1800.47 0,-1800.47 105,-1800.47 210,-1800.47 315,-1800.47 420,-1800.47 525,-1800.47 -125,-1735.51 129.92,-1735.51 -525,-1708.69 -420,-1708.69 -315,-1708.69 -210,-1708.69 210,-1708.69 315,-1708.69 420,-1708.69 525,-1708.69 -525,-1616.91 -420,-1616.91 -315,-1616.91 -210,-1616.91 210,-1616.91 315,-1616.91 420,-1616.91 525,-1616.91 -525,-1525.13 -420,-1525.13 -315,-1525.13 -210,-1525.13 210,-1525.13 315,-1525.13 420,-1525.13 525,-1525.13 -525,-1433.34 -420,-1433.34 -315,-1433.34 -210,-1433.34 210,-1433.34 315,-1433.34 420,-1433.34 525,-1433.34 -125,-1400.47 129.92,-1400.47
S3: R21.1 R21.2 R21.3 TP9.1 U3.2 | length 2021.8
  LAYER2 w50: U3.2 2240,-1593.93 2240,-1930.71 2269.29,-1960 3737.6,-1960 TP9.1
  other v1: 1725,-1800.47 1830,-1800.47 1935,-1800.47 2040,-1800.47 2145,-1800.47 2250,-1800.47 2355,-1800.47 2460,-1800.47 2565,-1800.47 2670,-1800.47 2775,-1800.47 2125,-1735.51 2379.92,-1735.51 1725,-1708.69 1830,-1708.69 1935,-1708.69 2040,-1708.69 2460,-1708.69 2565,-1708.69 2670,-1708.69 2775,-1708.69 1725,-1616.91 1830,-1616.91 1935,-1616.91 2040,-1616.91 2460,-1616.91 2565,-1616.91 2670,-1616.91 2775,-1616.91 1725,-1525.13 1830,-1525.13 1935,-1525.13 2040,-1525.13 2460,-1525.13 2565,-1525.13 2670,-1525.13 2775,-1525.13 1725,-1433.34 1830,-1433.34 1935,-1433.34 2040,-1433.34 2460,-1433.34 2565,-1433.34 2670,-1433.34 2775,-1433.34 2125,-1400.47 2379.92,-1400.47
pads on no net: MH1.3 MH2.3 MH3.3 MH4.3
copper on no net: | length 43860
  TOP w10: -4950,-4280 5050,-4280 5050,7650 -4950,7650 -4950,-4280

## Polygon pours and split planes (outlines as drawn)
S1 on TOP "TOP_S1" (solid, pour order 76): -3258.37,402.71 -3258.37,-1887.29 -1238.37,-1887.29 -1238.37,402.71
S3 on TOP "TOP_S3" (solid, pour order 70): 1240,393.16 1240,-1896.84 3260,-1896.84 3260,393.16
S2 on TOP "TOP_S2" (solid, pour order 69): -1010,393.16 -1010,-1896.84 1010,-1896.84 1010,393.16
MidpointC on TOP "TOP_MIDPOINT" (solid, pour order 89): 1169.9,-2715.35 2880,-2715.35 2880,-4155.36 1169.9,-4155.35
MidpointB on TOP "TOP_MIDPOINT" (solid, pour order 88): -1120,-2715.35 1150,-2715.35 1150,-4155.36 -1120,-4155.35
MidpointA on TOP "TOP_MIDPOINT" (solid, pour order 46): -2860,-2715.35 -1090,-2715.35 -1090,-4155.36 -2860,-4155.35
-Vin on TOP "TOP--VIN" (solid, remove dead copper, pour order 33): -1269.53,7300 -2110,7300 ccw(c-2110.01,7160.01) -2250,7160 -2250,6460 -4850,6460 -4850,540 ccw(c-4809.92,540) -4809.92,499.92 -4030,499.92 -4030,570 4080,570 cw(c4080,550) 4100,550 4100,499.67 4919.67,499.67 ccw(c4919.67,520) 4940,520 4940,1490 4940,6410 ccw(c4900.01,6410.01) 4900,6450 -1010,6460 -1010,7200 ccw(c-1109.98,7200.02) -1110,7300
MidpointC on LAYER3 "LAYER2_MIDPOINT" (solid, pour order 99): 1665.33,-2720.18 2875.33,-2720.18 2875.33,-4160.18 1665.33,-4160.18
MidpointA on LAYER3 "LAYER2_MIDPOINT" (solid, pour order 97): -2850,-2720 -1640,-2720 -1640,-4160 -2850,-4160
MidpointB on LAYER3 "LAYER2_MIDPOINT" (solid, pour order 98): -584.67,-2720.18 625.33,-2720.18 625.33,-4160.18 -584.67,-4160.18
S2 on LAYER3 "TOP_S1" (solid, pour order 80): -1008.37,402.71 -1008.37,-1887.29 1011.63,-1887.29 1011.63,402.71
S3 on LAYER3 "TOP_S1" (solid, pour order 77): 1230,423.46 1230,-1866.54 3250,-1866.54 3250,423.46
S1 on LAYER3 "TOP_S1" (solid, pour order 39): -3260,403.46 -3260,-1886.54 -1240,-1886.54 -1240,403.46
-Vin on LAYER3 "LAYER3-VIN" (solid, remove dead copper, pour order 31): -1269.53,7300 -2110,7300 ccw(c-2110.01,7160.01) -2250,7160 -2250,6460 -4850,6460 -4850,530 ccw(c-4820,530) -4820,500 -4060,500 ccw(c-4060,530) -4030,530 -4030,549.99 cw(c-4019.98,549.99) -4019.99,560.01 4080.01,569.98 cw(c4080.04,550.01) 4100,550.01 4100,530 ccw(c4130,530) 4130,500 4900,500 ccw(c4900,540) 4940,540 4940,1490 4940,6410 ccw(c4900.01,6410.01) 4900,6450 -1010,6460 -1010,7200 ccw(c-1109.98,7200.02) -1110,7300
+VIN on BOTTOM "BOTTOM+VIN" (solid, pour order 35): 2400.01,7170 2400.01,6450 4900,6450 cw(c4895.01,6405.01) 4940,6400 4940,1310 cw(c4870,1310) 4870,1240 4160,1240 ccw(c4160,1180) 4100,1180 4100,420 ccw(c4150,420) 4150,370 4880,370 cw(c4880,310) 4940,310 4940,-850 cw(c4880.01,-850.01) 4880,-910 -4790,-910 cw(c-4790,-850.01) -4849.99,-850.01 -4849.99,310.01 cw(c-4786.72,293.8) -4820,350 cw(c-4780.86,323.79) -4790,370 -4100,370 ccw(c-4100,440) -4029.99,440.01 -4029.99,1199.99 ccw(c-4070,1199.99) -4070,1240 -4810,1240 cw(c-4810,1279.99) -4849.99,1279.99 -4849.99,6420.04 cw(c-4810.1,6420.04) -4810.03,6459.93 1250.01,6450 1250.01,7160 cw(c1380,7160) 1380.01,7290 2280.01,7290 cw(c2280.01,7170)
-Vin on BOTTOM "-VIN_L04_P096" (solid, pour order 96): -1000,6650 -1000,7300 -2000,7300 -2000,6650
+VIN on BOTTOM "+VIN_L04_P023" (solid, pour order 23): 1155,6685 cw(c1155,6705) 1135,6705 1135,7265 cw(c1155,7265) 1155,7285 2040,7285 cw(c2040,7265) 2060,7265 2060,6630 cw(c2040,6630) 2040,6610 1430,6610 cw(c1430,6630) 1410,6630 1410,6665 ccw(c1390,6665) 1390,6685
NetR13_2 on BOTTOM "NETR13_2_L04_P018" (solid, pour order 18): -660,6685 ccw(c-660,6705) -640,6705 -640,7240 ccw(c-660,7240) -660,7260 -845,7260 ccw(c-845,7240) -865,7240 -865,6705 ccw(c-845,6705) -845,6685 -740,6685
NetR1_2 on BOTTOM "NETR1_2_L04_P022" (solid, pour order 22): 940,6685 ccw(c940,6705) 960,6705 960,7240 ccw(c940,7240) 940,7260 755,7260 ccw(c755,7240) 735,7240 735,6705 ccw(c755,6705) 755,6685 860,6685
NetR4_2 on BOTTOM "NETR4_2_L04_P021" (solid, pour order 21): 540,6685 ccw(c540,6705) 560,6705 560,7240 ccw(c540,7240) 540,7260 355,7260 ccw(c355,7240) 335,7240 335,6705 ccw(c355,6705) 355,6685 460,6685
NetR7_2 on BOTTOM "NETR7_2_L04_P020" (solid, pour order 20): 140,6685 ccw(c140,6705) 160,6705 160,7240 ccw(c140,7240) 140,7260 -45,7260 ccw(c-45,7240) -65,7240 -65,6705 ccw(c-45,6705) -45,6685 60,6685
NetR10_2 on BOTTOM "NETR10_2_L04_P019" (solid, pour order 19): -260,6685 ccw(c-260,6705) -240,6705 -240,7240 ccw(c-260,7240) -260,7260 -445,7260 ccw(c-445,7240) -465,7240 -465,6705 ccw(c-445,6705) -445,6685 -340,6685
MidpointC on BOTTOM "LAYER2_MIDPOINT" (solid, pour order 95): 1186.46,-2715 2880,-2715 2880,-4155 1186.46,-4155
MidpointB on BOTTOM "LAYER2_MIDPOINT" (solid, pour order 94): -1060,-2715 1148.23,-2715 1148.23,-4155 -1060,-4155
MidpointA on BOTTOM "LAYER2_MIDPOINT" (solid, pour order 93): -2860,-2715 -1040,-2715 -1040,-4155 -2860,-4155
+VIN on LAYER2 "LAYER2+VIN" (solid, pour order 37): 2400.01,7170 2400.01,6450 4900,6450 cw(c4895.01,6405.01) 4940,6400 4940,1310 cw(c4870,1310) 4870,1240 4160,1240 ccw(c4160,1180) 4100,1180 4100,420 ccw(c4150,420) 4150,370 4880,370 cw(c4880,310) 4940,310 4940,-850 cw(c4880.01,-850.01) 4880,-910 -4790,-910 cw(c-4790,-850.01) -4849.99,-850.01 -4849.99,290.01 cw(c-4770,290.01) -4770,370 -4100,370 ccw(c-4100,440) -4029.99,440.01 -4029.99,1240 -4810,1240 cw(c-4810,1279.99) -4849.99,1279.99 -4849.99,6420.04 cw(c-4810.1,6420.04) -4810.03,6459.93 1250.01,6450 1250.01,7160 cw(c1380,7160) 1380.01,7290 2280.01,7290 cw(c2280.01,7170)
MidpointB on LAYER2 "LAYER2_MIDPOINT" (solid, pour order 84): -590,-2715 590,-2715 590,-4155 -590,-4155
MidpointC on LAYER2 "LAYER2_MIDPOINT" (solid, pour order 85): 1660,-2715 2880,-2715 2880,-4155 1660,-4155
MidpointA on LAYER2 "LAYER2_MIDPOINT" (solid, pour order 45): -2860,-2715 -1650,-2715 -1650,-4155 -2860,-4155
no net on Top Solder "NONET_L01_P075" (solid): -1300,-2710 -960,-2710 -960,-4160 -1300,-4160
no net on Top Solder "NONET_L01_P075" (solid): 965,-2710 1290,-2710 1290,-4160 965,-4160
no net on Bottom Solder "NONET_L01_P075" (solid, pour order 75): -1300,-2710 -960,-2710 -960,-4160 -1300,-4160
no net on Bottom Solder "NONET_L01_P075" (solid): 965,-2710 1290,-2710 1290,-4160 965,-4160

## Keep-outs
TOP:
  rectangle: -1200,-4200 -1050,-2680
  rectangle: 1055.62,-4170 1205.62,-2706.23
BOTTOM:
  rectangle: -1200,-4170 -1050,-2680
  rectangle: 1055.62,-4170 1205.62,-2706.23

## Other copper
TOP:
  text "1" at 3930,-3780 h100
LAYER2:
  text "2" at 3977.28,-3780 h100
LAYER3:
  text "3" at 4039.49,-3778.8 h100
BOTTOM:
  text "4" at 4101.28,-3780 h100

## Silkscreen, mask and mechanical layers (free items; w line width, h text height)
Top Overlay:
  drawing of 22 lines, arcs and shapes, not listed
  text "PSU Connections" at -400,7391.48 h125
  text "CVR Shield" at -3920,761.18 h100
  text "CVR Shield" at 3440,721.18 h100
  text "Inductor" at 4420,221.04 h100
  text "Inductor" at -4660,211.04 h100
  text "V+" at -1174.1,-1380 h100
  text "V+" at -3904.1,-1468.23 h100
  text "V+" at 3807.44,-1471.06 h100
  text "V-" at -1160,-2000 h100
  text "V-" at -3894.42,-2048.23 h100
  text "V-" at 3807.12,-2051.06 h100
  text "Mid" at -1190,-2588.96 h100
  text "Mid" at -3920.96,-2637.19 h100
  text "Mid" at 3780.57,-2640.02 h100
  text "Module A" at -2450,-3348.96 h100
  text "Module B" at -170,-3368.96 h100
  text "Module C" at 2070,-3368.89 h100
  text "XM3 Paralleling Board Rev1" at -4760,-3621.13 h100
  text "04/10/2024" at -4750,-3748.82 h100
  text "MID" at -1840,-3880 h100 r90
  text "MID" at 420,-3880 h100 r90
  text "MID" at 2660,-3880 h100 r90
Bottom Overlay:
  text "Bleed Resistors R1-R18" at 670,7381.48 h125
Top Solder:
  rectangle: 3903.2,-3803.62 4178.2,-3693.62
Bottom Solder:
  rectangle: 3905,-3805 4180,-3695
ASSEMBLY_DETAIL:
  lines w15: 5260.47,-1520 5670.38,-1520 7000,-1520 8099.69,-1520 8749.52,-1520 ; 5260.47,-1400 5670.38,-1400 7000,-1400 8099.69,-1400 8749.52,-1400 ; 5260.47,-1280 5670.38,-1280 7000,-1280 8099.69,-1280 8749.52,-1280 ; 5260.47,-1160 5670.38,-1160 7000,-1160 8099.69,-1160 8749.52,-1160 ; 5260.47,-1040 5670.38,-1040 7000,-1040 8099.69,-1040 8749.52,-1040 ; 5260.47,-920 5670.38,-920 7000,-920 8099.69,-920 8749.52,-920 ; 5260.47,-800 5670.38,-800 7000,-800 8099.69,-800 8749.52,-800 ; 5260.47,-680 5670.38,-680 7000,-680 8099.69,-680 8749.52,-680 ; 5260.47,-560 5670.38,-560 7000,-560 8099.69,-560 8749.52,-560 ; 5260.47,-440 5670.38,-440 7000,-440 8099.69,-440 8749.52,-440 ; 5260.47,-320 5670.38,-320 7000,-320 8099.69,-320 8749.52,-320 ; 5260.47,-200 5670.38,-200 7000,-200 8099.69,-200 8749.52,-200 ; 5260.47,-80 8749.52,-80 ; 5670.38,40 5670.38,-1640 ; 7000,40 7000,-1640 ; 8099.69,40 8099.69,-1640 ; 5670.38,-1640 7000,-1640 ; 5670.38,-1640 5260.47,-1640 5260.47,40 8749.52,40 8749.52,-1640 8099.69,-1640 ; 7000,-1640 8099.69,-1640
  text "Layer" at 5330.47,-50 h60
  text "Name" at 5740.38,-50 h60
  text "Material" at 7070,-50 h60
  text "Thickness" at 8169.69,-50 h60
  text "Top Overlay" at 5740.38,-170 h60
  text "Top Solder" at 5740.38,-290 h60
  text "Purple" at 7070,-290 h60
  text "Top Surface Finish" at 5740.38,-410 h60
  text "ENIG Nickel, Gold" at 7070,-410 h60
  text "1" at 5330.47,-530 h60
  text "TOP" at 5740.38,-530 h60
  text "2oz Cu" at 7070,-530 h60
  text "2.68mil" at 8169.69,-530 h60
  text "Dielectric 1" at 5740.38,-650 h60
  text "FR-4" at 7070,-650 h60
  text "8.00mil" at 8169.69,-650 h60
  text "2" at 5330.47,-770 h60
  text "LAYER2" at 5740.38,-770 h60
  text "2oz Cu" at 7070,-770 h60
  text "2.68mil" at 8169.69,-770 h60
  text "Dielectric2" at 5740.38,-890 h60
  text "FR-4" at 7070,-890 h60
  text "65.28mil" at 8169.69,-890 h60
  text "3" at 5330.47,-1010 h60
  text "LAYER3" at 5740.38,-1010 h60
  text "2oz Cu" at 7070,-1010 h60
  text "2.68mil" at 8169.69,-1010 h60
  text "Dielectric3" at 5740.38,-1130 h60
  text "FR-4" at 7070,-1130 h60
  text "8.00mil" at 8169.69,-1130 h60
  text "4" at 5330.47,-1250 h60
  text "BOTTOM" at 5740.38,-1250 h60
  text "2oz Cu" at 7070,-1250 h60
  text "2.68mil" at 8169.69,-1250 h60
  text "Bottom Surface Finish" at 5740.38,-1370 h60
  text "ENIG Nickel, Gold" at 7070,-1370 h60
  text "Bottom Solder" at 5740.38,-1490 h60
  text "Purple" at 7070,-1490 h60
  text "Bottom Overlay" at 5740.38,-1610 h60
  text "Total board thickness:" at 5330.47,-1730 h60
  text "92.00mil" at 8169.69,-1730 h60
Drill Drawing:
  circle w10: c5327.43,-3206.67 r33.33
  circle w10: c5327.43,-3656.67 r20
  circle w10: c5327.43,-3656.67 r33.33
  lines w10: 5294.09,-3823.33 5310.76,-3823.33 5310.76,-3840 5344.09,-3840 5344.09,-3823.33 5360.76,-3823.33 5360.76,-3790 5344.09,-3790 5344.09,-3773.33 5310.76,-3773.33 5310.76,-3790 5294.09,-3790 5294.09,-3823.33 ; 5294.09,-3523.33 5310.76,-3523.33 5327.43,-3540 5344.09,-3523.33 5360.76,-3523.33 5344.09,-3506.67 5360.76,-3490 5344.09,-3490 5327.43,-3473.33 5310.76,-3490 5294.09,-3490 5310.76,-3506.67 5294.09,-3523.33 ; 5294.09,-3390 5360.76,-3390 5360.76,-3323.33 5294.09,-3323.33 5294.09,-3390 ; 5294.09,-3056.67 5327.43,-3090 5360.76,-3056.67 5327.43,-3023.33 5294.09,-3056.67 ; 5294.09,-2873.33 5360.76,-2873.33 5327.43,-2940 5294.09,-2873.33 ; 5294.09,-2790 5327.43,-2773.33 5360.76,-2790 5344.09,-2756.67 5360.76,-2723.33 5327.43,-2740 5294.09,-2723.33 5310.76,-2756.67 5294.09,-2790 ; 5294.09,-2640 5294.09,-2623.33 5310.76,-2606.67 5294.09,-2590 5294.09,-2573.33 5310.76,-2573.33 5327.43,-2590 5344.09,-2573.33 5360.76,-2573.33 5360.76,-2590 5344.09,-2606.67 5360.76,-2623.33 5360.76,-2640 5344.09,-2640 5327.43,-2623.33 5310.76,-2640 5294.09,-2640
  lines w15: 5234.3,-3885 17768.77,-3885 ; 5234.3,-2535 17768.77,-2535 ; 5785.18,-4035 5785.18,-2385 ; 6385.02,-4035 6385.02,-2385 ; 7544.68,-4035 7544.68,-2385 ; 8050.56,-4035 8050.56,-2385 ; 8784.36,-4035 8784.36,-2385 ; 9974.01,-4035 9974.01,-2385 ; 10563.86,-4035 10563.86,-2385 ; 11309.66,-4035 11309.66,-2385 ; 12539.3,-4035 12539.3,-2385 ; 13872.9,-4035 13872.9,-2385 ; 15206.51,-4035 15206.51,-2385 ; 16366.17,-4035 16366.17,-2385 ; 5234.3,-4035 17768.77,-4035 17768.77,-2385 5234.3,-2385 5234.3,-4035
  text "Symbol" at 5324.3,-2490 h72
  text "Count" at 5830.18,-2490 h72
  text "Hole Size" at 6430.02,-2490 h72
  text "Plated" at 7589.68,-2490 h72
  text "Hole Type" at 8095.56,-2490 h72
  text "Drill Layer Pair" at 8829.36,-2490 h72
  text "Via/Pad" at 10019.01,-2490 h72
  text "Pad Shape" at 10608.86,-2490 h72
  text "Template" at 11354.66,-2490 h72
  text "Hole Tolerance (+)" at 12584.3,-2490 h72
  text "Hole Tolerance (-)" at 13917.9,-2490 h72
  text "Hole Length" at 15251.51,-2490 h72
  text "Routed Path Length" at 16411.17,-2490 h72
  text "375" at 5830.18,-2640 h60
  text "19.69mil (0.500mm)" at 6430.02,-2640 h60
  text "PTH" at 7589.68,-2640 h60
  text "Round" at 8095.56,-2640 h60
  text "TOP - BOTTOM" at 8829.36,-2640 h60
  text "Via" at 10019.01,-2640 h60
  text "Rounded" at 10608.86,-2640 h60
  text "v100h50" at 11354.66,-2640 h60
  text "-" at 15251.51,-2640 h60
  text "-" at 16411.17,-2640 h60
  text "9" at 5830.18,-2790 h60
  text "62.99mil (1.600mm)" at 6430.02,-2790 h60
  text "PTH" at 7589.68,-2790 h60
  text "Round" at 8095.56,-2790 h60
  text "TOP - BOTTOM" at 8829.36,-2790 h60
  text "Pad" at 10019.01,-2790 h60
  text "Rounded" at 10608.86,-2790 h60
  text "c210h160" at 11354.66,-2790 h60
  text "-" at 15251.51,-2790 h60
  text "-" at 16411.17,-2790 h60
  text "48" at 5830.18,-2940 h60
  text "76.77mil (1.950mm)" at 6430.02,-2940 h60
  text "PTH" at 7589.68,-2940 h60
  text "Round" at 8095.56,-2940 h60
  text "TOP - BOTTOM" at 8829.36,-2940 h60
  text "Pad" at 10019.01,-2940 h60
  text "(Mixed)" at 10608.86,-2940 h60
  text "(Mixed)" at 11354.66,-2940 h60
  text "-" at 15251.51,-2940 h60
  text "-" at 16411.17,-2940 h60
  text "54" at 5830.18,-3090 h60
  text "103.94mil (2.640mm)" at 6430.02,-3090 h60
  text "PTH" at 7589.68,-3090 h60
  text "Round" at 8095.56,-3090 h60
  text "TOP - BOTTOM" at 8829.36,-3090 h60
  text "Pad" at 10019.01,-3090 h60
  text "Rounded" at 10608.86,-3090 h60
  text "c381h264z152(Tol0-0)" at 11354.66,-3090 h60
  text "0.00mil (0.000mm)" at 12584.3,-3090 h60
  text "0.00mil (0.000mm)" at 13917.9,-3090 h60
  text "-" at 15251.51,-3090 h60
  text "-" at 16411.17,-3090 h60
  text "12" at 5830.18,-3240 h60
  text "129.92mil (3.300mm)" at 6430.02,-3240 h60
  text "PTH" at 7589.68,-3240 h60
  text "Round" at 8095.56,-3240 h60
  text "TOP - BOTTOM" at 8829.36,-3240 h60
  text "Via" at 10019.01,-3240 h60
  text "Rounded" at 10608.86,-3240 h60
  text "v400h330" at 11354.66,-3240 h60
  text "-" at 15251.51,-3240 h60
  text "-" at 16411.17,-3240 h60
  text "9" at 5830.18,-3390 h60
  text "170.00mil (4.318mm)" at 6430.02,-3390 h60
  text "PTH" at 7589.68,-3390 h60
  text "Round" at 8095.56,-3390 h60
  text "TOP - BOTTOM" at 8829.36,-3390 h60
  text "Pad" at 10019.01,-3390 h60
  text "(Mixed)" at 10608.86,-3390 h60
  text "(Mixed)" at 11354.66,-3390 h60
  text "0.00mil (0.000mm)" at 12584.3,-3390 h60
  text "0.00mil (0.000mm)" at 13917.9,-3390 h60
  text "-" at 15251.51,-3390 h60
  text "-" at 16411.17,-3390 h60
  text "9" at 5830.18,-3540 h60
  text "170.00mil (4.318mm)" at 6430.02,-3540 h60
  text "PTH" at 7589.68,-3540 h60
  text "Slot" at 8095.56,-3540 h60
  text "TOP - BOTTOM" at 8829.36,-3540 h60
  text "Pad" at 10019.01,-3540 h60
  text "Rounded" at 10608.86,-3540 h60
  text "(Mixed)" at 11354.66,-3540 h60
  text "0.00mil (0.000mm)" at 12584.3,-3540 h60
  text "0.00mil (0.000mm)" at 13917.9,-3540 h60
  text "240.00mil (6.096mm)" at 15251.51,-3540 h60
  text "70.00mil (1.778mm)" at 16411.17,-3540 h60
  text "4" at 5830.18,-3690 h60
  text "177.17mil (4.500mm)" at 6430.02,-3690 h60
  text "PTH" at 7589.68,-3690 h60
  text "Round" at 8095.56,-3690 h60
  text "TOP - BOTTOM" at 8829.36,-3690 h60
  text "Pad" at 10019.01,-3690 h60
  text "Rounded" at 10608.86,-3690 h60
  text "c550h450" at 11354.66,-3690 h60
  text "-" at 15251.51,-3690 h60
  text "-" at 16411.17,-3690 h60
  text "9" at 5830.18,-3840 h60
  text "248.03mil (6.300mm)" at 6430.02,-3840 h60
  text "PTH" at 7589.68,-3840 h60
  text "Round" at 8095.56,-3840 h60
  text "TOP - BOTTOM" at 8829.36,-3840 h60
  text "Pad" at 10019.01,-3840 h60
  text "Rounded" at 10608.86,-3840 h60
  text "c830h630" at 11354.66,-3840 h60
  text "-" at 15251.51,-3840 h60
  text "-" at 16411.17,-3840 h60
  text "529 Total" at 5830.18,-3990 h60
  text "Slot definitions :" at 5324.3,-4134.97 h60
  text "Routed Path Length" at 6356.99,-4134.97 h60
  text "= Calculated from tool start centre position to tool end centre position." at 7459.66,-4134.97 h60
  text "Hole Length" at 6356.99,-4234.95 h60
  text "= Routed Path Length + Tool Size = Slot length as defined in the PCB layout" at 7049.79,-4234.95 h60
